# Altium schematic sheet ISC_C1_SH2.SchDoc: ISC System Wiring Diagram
size B; DrawnBy: Filiberto Clara; Engineer: Filiberto Clara; Organization: LIGO Laboratory; Address1: California Institute of Technology; Address2: Massachusetts Institute of Technology; SheetNumber: 2; SheetTotal: 37
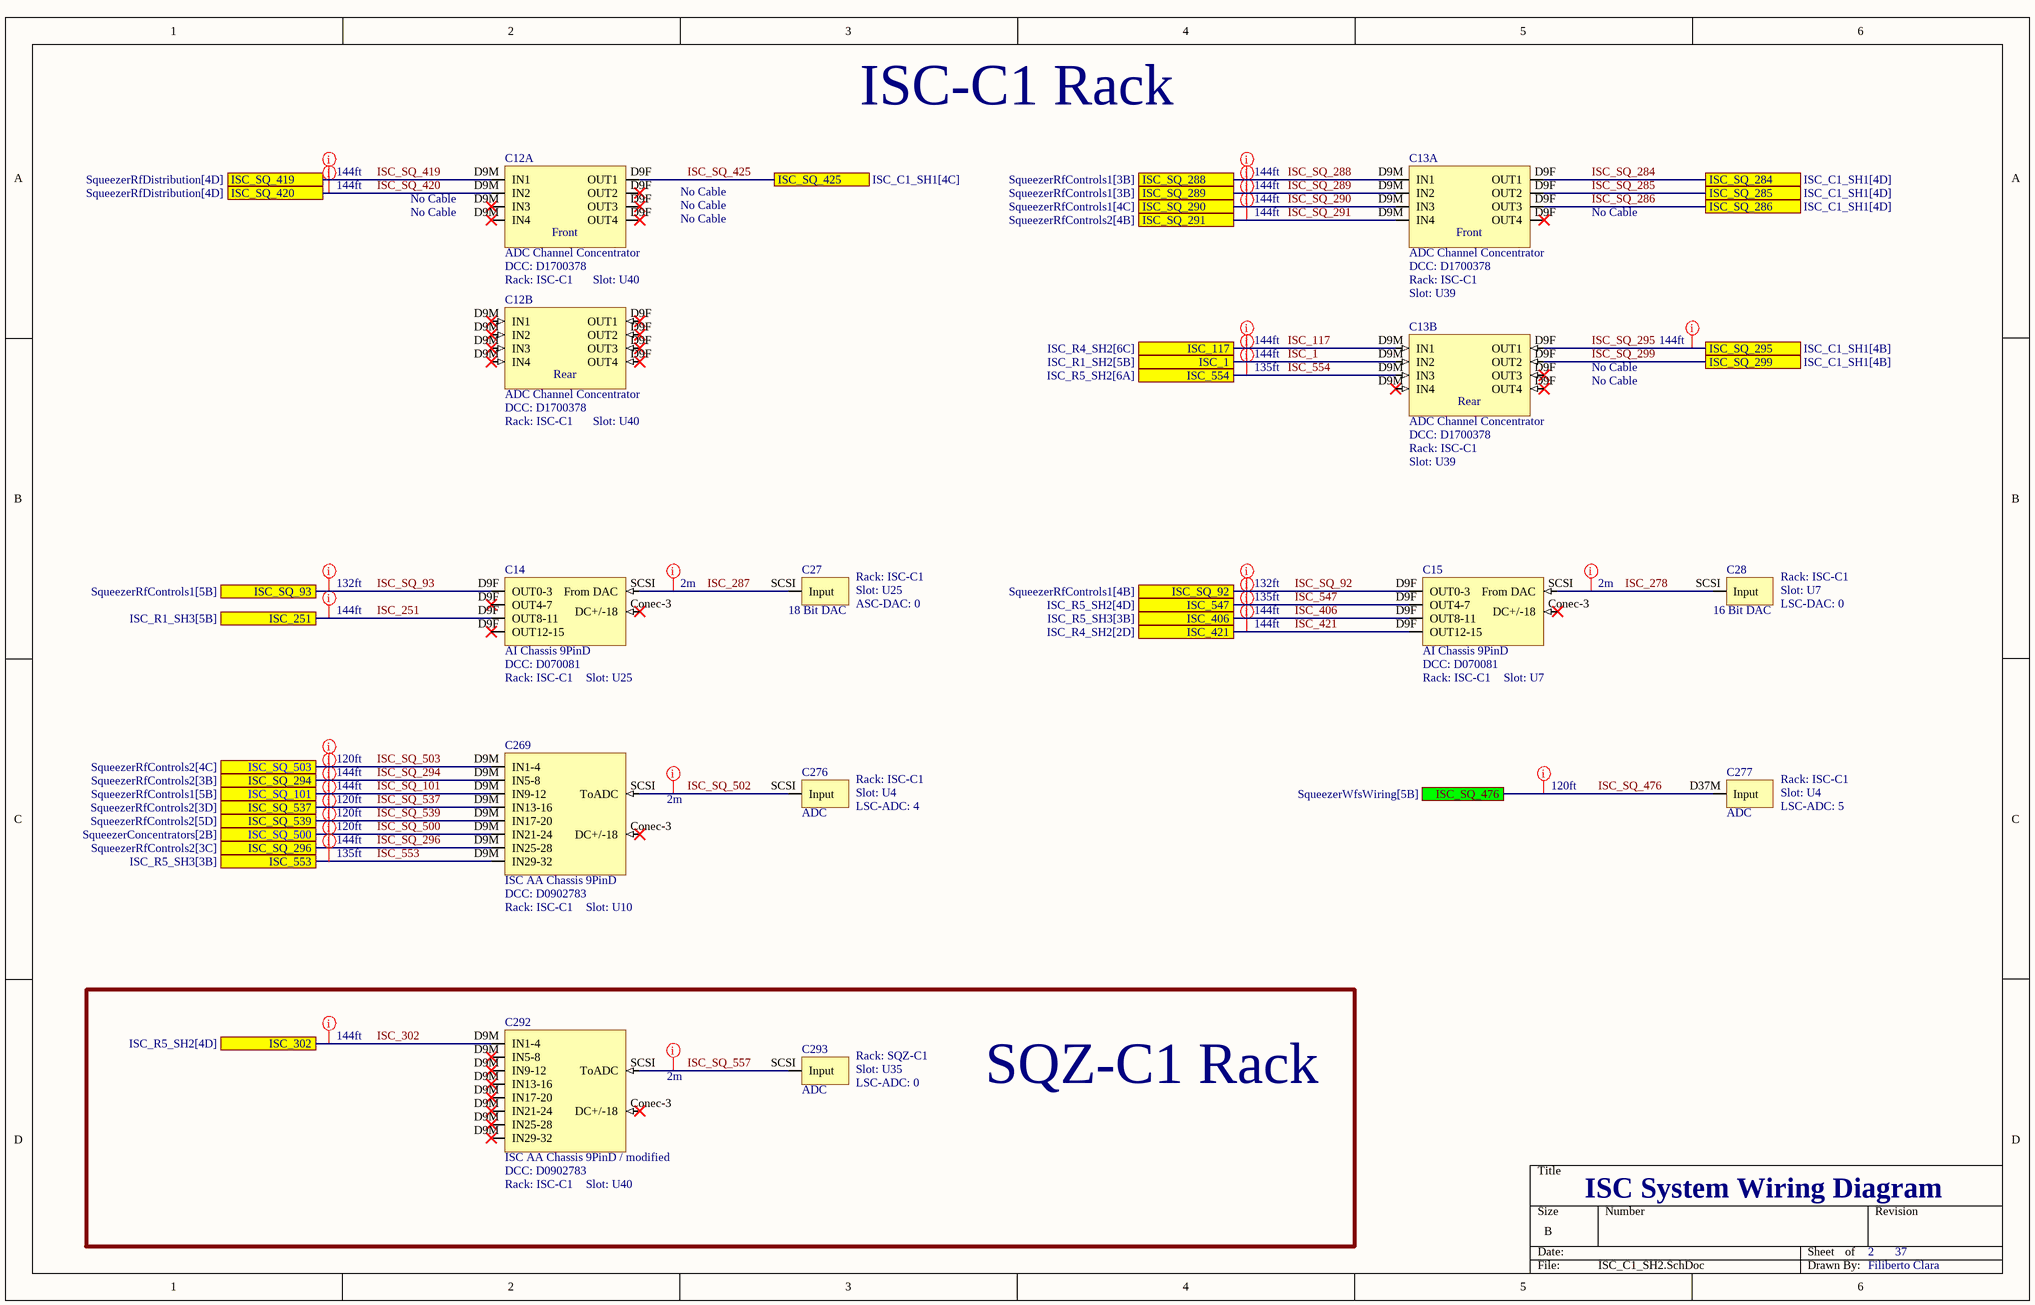
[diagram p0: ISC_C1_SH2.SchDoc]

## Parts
C12  ADC Channel Concentrator  DCC: D1700378  Rack: ISC-C1  Slot: U40  (parts A,B of 2)
C13  ADC Channel Concentrator  DCC: D1700378  Rack: ISC-C1  Slot: U39  (parts A,B of 2)
C14  AI Chassis 9PinD  DCC: D070081  Rack: ISC-C1  Slot: U25
C15  AI Chassis 9PinD  DCC: D070081  Rack: ISC-C1  Slot: U7
C27  18 Bit DAC  Rack: ISC-C1  Slot: U25  ASC-DAC: 0
C28  16 Bit DAC  Rack: ISC-C1  Slot: U7  LSC-DAC: 0
C269  ISC AA Chassis 9PinD  DCC: D0902783  Rack: ISC-C1  Slot: U10
C276  ADC  Rack: ISC-C1  Slot: U4  LSC-ADC: 4
C277  ADC  Rack: ISC-C1  Slot: U4  LSC-ADC: 5
C292  ISC AA Chassis 9PinD / modified  DCC: D0902783  Rack: ISC-C1  Slot: U40
C293  ADC  Rack: SQZ-C1  Slot: U35  LSC-ADC: 0

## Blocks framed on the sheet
SQZ-C1 Rack: C292 C293

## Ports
ISC_1 (see ISC_R1_SH2[5B]), ISC_117 (see ISC_R4_SH2[6C]), ISC_251 (see ISC_R1_SH3[5B]), ISC_302 (see ISC_R5_SH2[4D]), ISC_406 (see ISC_R5_SH3[3B]), ISC_421 (see ISC_R4_SH2[2D]), ISC_547 (see ISC_R5_SH2[4D]), ISC_553 (see ISC_R5_SH3[3B]), ISC_554 (see ISC_R5_SH2[6A]), ISC_SQ_92 (see SqueezerRfControls1[4B]), ISC_SQ_93 (see SqueezerRfControls1[5B]), ISC_SQ_101 (see SqueezerRfControls1[5B]), ISC_SQ_284 (see ISC_C1_SH1[4D]), ISC_SQ_285 (see ISC_C1_SH1[4D]), ISC_SQ_286 (see ISC_C1_SH1[4D]), ISC_SQ_288 (see SqueezerRfControls1[3B]), ISC_SQ_289 (see SqueezerRfControls1[3B]), ISC_SQ_290 (see SqueezerRfControls1[4C]), ISC_SQ_291 (see SqueezerRfControls2[4B]), ISC_SQ_294 (see SqueezerRfControls2[3B]), ISC_SQ_295 (see ISC_C1_SH1[4B]), ISC_SQ_296 (see SqueezerRfControls2[3C]), ISC_SQ_299 (see ISC_C1_SH1[4B]), ISC_SQ_419 (see SqueezerRfDistribution[4D]), ISC_SQ_420 (see SqueezerRfDistribution[4D]), ISC_SQ_425 (see ISC_C1_SH1[4C]), ISC_SQ_476 (see SqueezerWfsWiring[5B]), ISC_SQ_500 (see SqueezerConcentrators[2B]), ISC_SQ_503 (see SqueezerRfControls2[4C]), ISC_SQ_537 (see SqueezerRfControls2[3D]), ISC_SQ_539 (see SqueezerRfControls2[5D])

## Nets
ISC_1: C13.D9M(IN2) ; port ISC_1
ISC_117: C13.D9M(IN1) ; port ISC_117
ISC_251: C14.D9F(OUT8-11) ; port ISC_251
ISC_278: C15.SCSI(From_DAC) C28.SCSI(Input)
ISC_287: C14.SCSI(From_DAC) C27.SCSI(Input)
ISC_302: C292.D9M(IN1-4) ; port ISC_302
ISC_406: C15.D9F(OUT8-11) ; port ISC_406
ISC_421: C15.D9F(OUT12-15) ; port ISC_421
ISC_547: C15.D9F(OUT4-7) ; port ISC_547
ISC_553: C269.D9M(IN29-32) ; port ISC_553
ISC_554: C13.D9M(IN3) ; port ISC_554
ISC_SQ_92: C15.D9F(OUT0-3) ; port ISC_SQ_92
ISC_SQ_93: C14.D9F(OUT0-3) ; port ISC_SQ_93
ISC_SQ_101: C269.D9M(IN9-12) ; port ISC_SQ_101
ISC_SQ_284: C13.D9F(OUT1) ; port ISC_SQ_284
ISC_SQ_285: C13.D9F(OUT2) ; port ISC_SQ_285
ISC_SQ_286: C13.D9F(OUT3) ; port ISC_SQ_286
ISC_SQ_288: C13.D9M(IN1) ; port ISC_SQ_288
ISC_SQ_289: C13.D9M(IN2) ; port ISC_SQ_289
ISC_SQ_290: C13.D9M(IN3) ; port ISC_SQ_290
ISC_SQ_291: C13.D9M(IN4) ; port ISC_SQ_291
ISC_SQ_294: C269.D9M(IN5-8) ; port ISC_SQ_294
ISC_SQ_295: C13.D9F(OUT1) ; port ISC_SQ_295
ISC_SQ_296: C269.D9M(IN25-28) ; port ISC_SQ_296
ISC_SQ_299: C13.D9F(OUT2) ; port ISC_SQ_299
ISC_SQ_419: C12.D9M(IN1) ; port ISC_SQ_419
ISC_SQ_420: C12.D9M(IN2) ; port ISC_SQ_420
ISC_SQ_425: C12.D9F(OUT1) ; port ISC_SQ_425
ISC_SQ_476: C277.D37M(Input) ; port ISC_SQ_476
ISC_SQ_500: C269.D9M(IN21-24) ; port ISC_SQ_500
ISC_SQ_502: C269.SCSI(ToADC) C276.SCSI(Input)
ISC_SQ_503: C269.D9M(IN1-4) ; port ISC_SQ_503
ISC_SQ_537: C269.D9M(IN13-16) ; port ISC_SQ_537
ISC_SQ_539: C269.D9M(IN17-20) ; port ISC_SQ_539
ISC_SQ_557: C292.SCSI(ToADC) C293.SCSI(Input)

Not connected (* = marked no-connect by the designer): C14 Conec-3(DC+/-18)*; C15 Conec-3(DC+/-18)*; C269 Conec-3(DC+/-18)*; C292 Conec-3(DC+/-18)*

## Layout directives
Length: 144ft: ISC_1, ISC_117, ISC_251, ISC_302, ISC_406, ISC_421, ISC_SQ_101, ISC_SQ_288, ISC_SQ_289, ISC_SQ_290, ISC_SQ_291, ISC_SQ_294, ISC_SQ_295, ISC_SQ_296, ISC_SQ_419, ISC_SQ_420
Length: 2m: ISC_278, ISC_287, ISC_SQ_502, ISC_SQ_557
Length: 132ft: ISC_SQ_92, ISC_SQ_93
Length: 120ft: ISC_SQ_476, ISC_SQ_500, ISC_SQ_503, ISC_SQ_537, ISC_SQ_539
Length: 135ft: ISC_547, ISC_553, ISC_554

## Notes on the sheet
- ISC-C1 Rack
- (near C12) No Cable
- No Cable

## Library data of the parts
C12 C13 = ADC Channel Concentrator: Serial: Sxxxxxxx; System: ISC
C14 C15 = AI_9pinAll: Serial: Sxxxxxxx; System: ISC
C27 = DAC_18: Serial: Sxxxxxxx; System: ISC; DCC: tbd
C28 = DAC_18: 18 Bit DAC; Serial: Sxxxxxxx; System: ISC; DCC: tbd
C269 = AA_9pinAll: Serial: Sxxxxxxx
C276 C277 C293 = ADC-16: 16 Bit ADC; Serial: Sxxxxxxx; System: ISC; DCC: tbd
C292 = AA_9pinAll: ISC AA Chassis 9PinD; Serial: Sxxxxxxx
